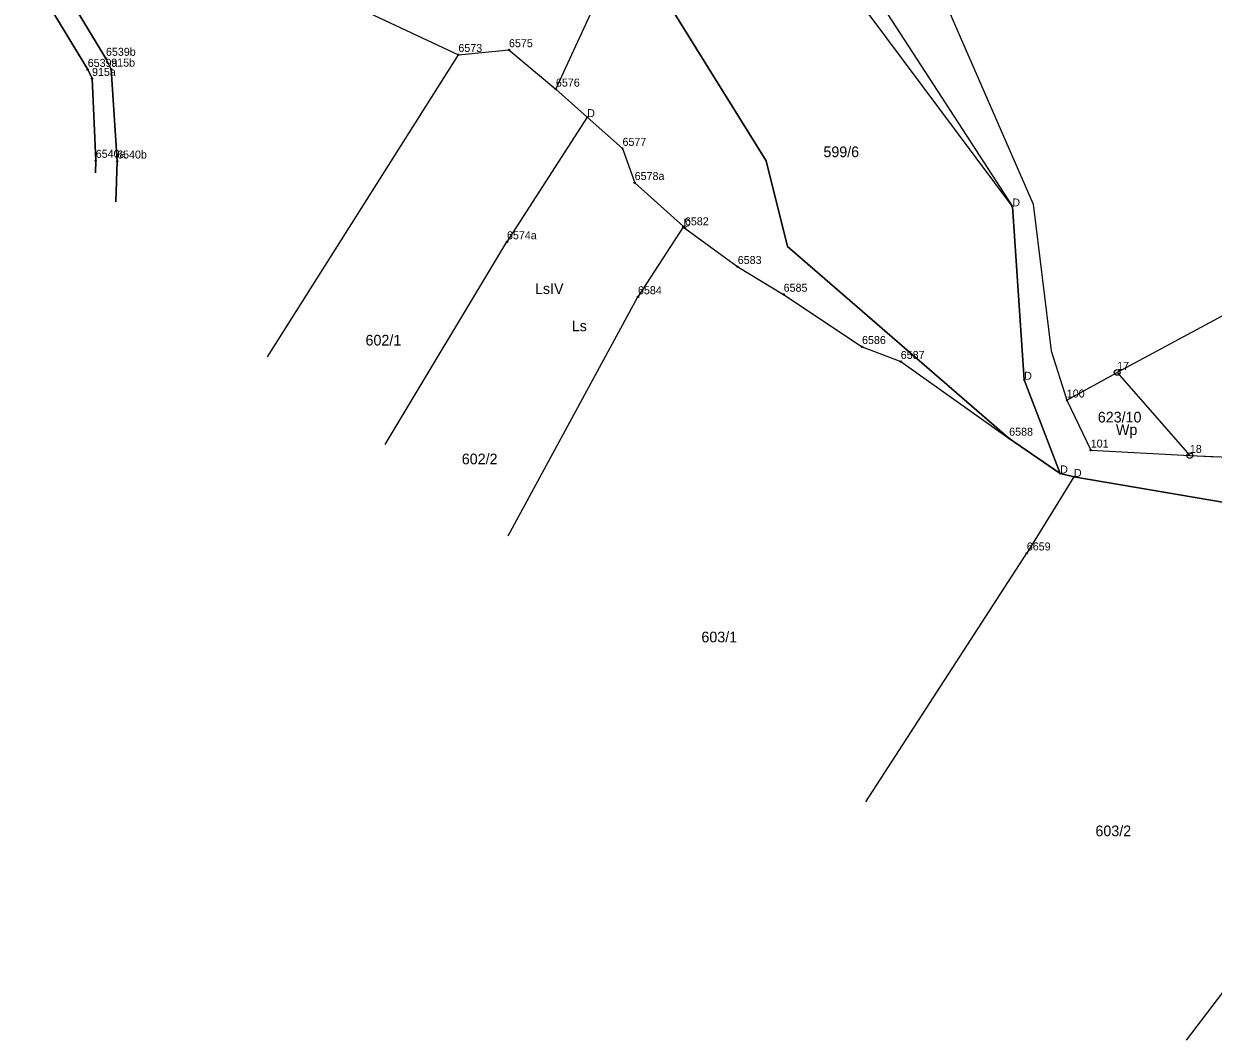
# Model space of a CAD drawing. Extents: x 7465393 to 7466459, y 5491258 to 5492404.
# Drawn here: x 7465794.3 to 7465961.5, y 5491455.4 to 5491598.3 of the extents above; entities that cross this region are included whole.
import ezdxf

# ---------------------------------------------------------------- set-up
doc = ezdxf.new("R2010")
doc.units = 0
for name, color, linetype in [('202-punkt graniczny', 7, 'Continuous'), ('202-punkt graniczny-Atr103', 7, 'Continuous'), ('203-punkt graniczny', 7, 'Continuous'), ('203-punkt graniczny-Atr103', 7, 'Continuous'), ('209-oznaczenie konturu klasyfikacyjnego', 7, 'Continuous'), ('210-oznaczenie konturu użytku gruntowego', 7, 'Continuous'), ('211-numer działki ewidencyjnej', 7, 'Continuous'), ('217-kontur klasyfikacyjny', 7, 'Continuous'), ('218-kontur użytku gruntowego', 7, 'Continuous'), ('219-działka ewidencyjna', 7, 'Continuous')]:
    doc.layers.add(name, color=color, linetype=linetype)

# ---------------------------------------------------------------- blocks, each defined once
blk = doc.blocks.new('203')
blk.add_circle((0, 0), 0.09)
blk = doc.blocks.new('202')
blk.add_circle((0, 0), 0.4)

msp = doc.modelspace()

# ---------------------------------------------------------------- linework, layer by layer
at = {"layer": '217-kontur klasyfikacyjny'}
for points in [[(7465796.9, 5491608.21), (7465805.83, 5491593.45)], [(7465898.65, 5491579.07), (7465880.35, 5491608.51)], [(7465803.27, 5491591.89), (7465794.28, 5491606.75)], [(7465805.83, 5491593.45), (7465806.57, 5491591.93)], [(7465803.87, 5491590.63), (7465803.27, 5491591.89)], [(7465806.57, 5491591.93), (7465807.4, 5491579.01)], [(7465804.4, 5491579.11), (7465803.87, 5491590.63)], [(7465804.34, 5491577.37), (7465804.4, 5491579.11)], [(7465807.4, 5491579.01), (7465807.2, 5491573.3)], [(7465901.61, 5491567.03), (7465898.65, 5491579.07)], [(7465932.79, 5491540.05), (7465901.61, 5491567.03)], [(7465939.96, 5491535.12), (7465932.79, 5491540.05)], [(7465941.89, 5491534.63), (7465939.96, 5491535.12)], [(7465980.11, 5491528.12), (7465941.89, 5491534.63)]]:
    msp.add_lwpolyline(points, dxfattribs=at)
at = {"layer": '218-kontur użytku gruntowego'}
for points in [[(7465890.56, 5491638.43), (7465933.24, 5491572.65)], [(7465933.24, 5491572.65), (7465892.52, 5491627.25)], [(7465805.83, 5491593.45), (7465796.9, 5491608.21)], [(7465880.35, 5491608.51), (7465898.65, 5491579.07)], [(7465794.28, 5491606.75), (7465803.27, 5491591.89)], [(7465923.67, 5491601.71), (7465936.16, 5491572.97)], [(7465806.57, 5491591.93), (7465805.83, 5491593.45)], [(7465803.27, 5491591.89), (7465803.87, 5491590.63)], [(7465807.4, 5491579.01), (7465806.57, 5491591.93)], [(7465803.87, 5491590.63), (7465804.4, 5491579.11)], [(7465804.4, 5491579.11), (7465804.34, 5491577.37)], [(7465807.2, 5491573.3), (7465807.4, 5491579.01)], [(7465898.65, 5491579.07), (7465901.61, 5491567.03)], [(7465934.9, 5491548.28), (7465933.24, 5491572.65)], [(7465936.16, 5491572.97), (7465938.68, 5491552.35)], [(7465901.61, 5491567.03), (7465932.79, 5491540.05)], [(7465938.68, 5491552.35), (7465940.89, 5491545.42)], [(7465939.96, 5491535.12), (7465934.9, 5491548.28)], [(7465940.89, 5491545.42), (7465947.97, 5491549.31)], [(7465947.97, 5491549.31), (7465958.19, 5491537.62)], [(7465940.89, 5491545.42), (7465944.26, 5491538.37)], [(7465932.79, 5491540.05), (7465939.96, 5491535.12)], [(7465944.26, 5491538.37), (7465958.19, 5491537.62)], [(7465958.19, 5491537.62), (7465962.06, 5491537.46)], [(7465941.89, 5491534.63), (7465939.96, 5491535.12)], [(7465980.11, 5491528.12), (7465941.89, 5491534.63)]]:
    msp.add_lwpolyline(points, dxfattribs=at)
at = {"layer": '219-działka ewidencyjna'}
for points in [[(7465933.24, 5491572.65), (7465892.52, 5491627.25)], [(7465796.9, 5491608.21), (7465805.83, 5491593.45)], [(7465794.28, 5491606.75), (7465803.27, 5491591.89)], [(7465869.08, 5491589.12), (7465875.59, 5491603.28)], [(7465839.89, 5491601.21), (7465855.37, 5491593.99)], [(7465805.83, 5491593.45), (7465806.57, 5491591.93)], [(7465828.54, 5491551.49), (7465855.37, 5491593.99)], [(7465855.37, 5491593.99), (7465862.48, 5491594.66)], [(7465862.48, 5491594.66), (7465869.08, 5491589.12)], [(7465803.27, 5491591.89), (7465803.87, 5491590.63)], [(7465806.57, 5491591.93), (7465807.4, 5491579.01)], [(7465803.87, 5491590.63), (7465804.4, 5491579.11)], [(7465873.48, 5491585.21), (7465869.08, 5491589.12)], [(7465873.48, 5491585.21), (7465862.2, 5491567.66)], [(7465873.48, 5491585.21), (7465878.44, 5491580.8)], [(7465878.44, 5491580.8), (7465880.15, 5491575.99)], [(7465804.34, 5491577.37), (7465804.4, 5491579.11)], [(7465807.2, 5491573.3), (7465807.4, 5491579.01)], [(7465886.99, 5491569.82), (7465880.15, 5491575.99)], [(7465933.24, 5491572.65), (7465934.9, 5491548.28)], [(7465989.35, 5491571.56), (7465947.97, 5491549.31)], [(7465886.99, 5491569.82), (7465880.61, 5491559.93)], [(7465886.99, 5491569.82), (7465887.21, 5491569.62)], [(7465887.21, 5491569.62), (7465894.64, 5491564.18)], [(7465845.09, 5491539.18), (7465862.2, 5491567.66)], [(7465894.64, 5491564.18), (7465901.09, 5491560.28)], [(7465862.35, 5491526.34), (7465880.61, 5491559.93)], [(7465901.09, 5491560.28), (7465912.11, 5491552.93)], [(7465912.11, 5491552.93), (7465917.55, 5491550.84)], [(7465917.55, 5491550.84), (7465932.79, 5491540.05)], [(7465934.9, 5491548.28), (7465939.96, 5491535.12)], [(7465940.89, 5491545.42), (7465947.97, 5491549.31)], [(7465947.97, 5491549.31), (7465958.19, 5491537.62)], [(7465940.89, 5491545.42), (7465944.26, 5491538.37)], [(7465939.96, 5491535.12), (7465932.79, 5491540.05)], [(7465944.26, 5491538.37), (7465958.19, 5491537.62)], [(7465958.19, 5491537.62), (7465980.12, 5491536.72)], [(7465941.89, 5491534.63), (7465935.27, 5491523.92)], [(7465939.96, 5491535.12), (7465941.89, 5491534.63)], [(7465941.89, 5491534.63), (7465980.11, 5491528.12)], [(7465912.65, 5491488.94), (7465935.27, 5491523.92)], [(7465957.71, 5491455.43), (7465969.3, 5491470.62)]]:
    msp.add_lwpolyline(points, dxfattribs=at)

# ---------------------------------------------------------------- block references
at = {"layer": '202-punkt graniczny'}
for p in [(7465947.97, 5491549.31), (7465958.19, 5491537.62)]:
    msp.add_blockref('202', p, dxfattribs=at)
at = {"layer": '203-punkt graniczny'}
for p in [(7465805.83, 5491593.45), (7465855.37, 5491593.99), (7465862.48, 5491594.66), (7465803.27, 5491591.89), (7465806.57, 5491591.93), (7465803.87, 5491590.63), (7465869.08, 5491589.12), (7465873.48, 5491585.21), (7465878.44, 5491580.8), (7465804.4, 5491579.11), (7465807.4, 5491579.01), (7465880.15, 5491575.99), (7465933.24, 5491572.65), (7465886.99, 5491569.82), (7465887.21, 5491569.62), (7465862.2, 5491567.66), (7465894.64, 5491564.18), (7465880.61, 5491559.93), (7465901.09, 5491560.28), (7465912.11, 5491552.93), (7465917.55, 5491550.84), (7465934.9, 5491548.28), (7465940.89, 5491545.42), (7465932.79, 5491540.05), (7465944.26, 5491538.37), (7465939.96, 5491535.12), (7465941.89, 5491534.63), (7465935.27, 5491523.92)]:
    msp.add_blockref('203', p, dxfattribs=at)

# ---------------------------------------------------------------- texts
at = {"layer": '202-punkt graniczny-Atr103'}
for s, p in [('17', (7465947.97, 5491549.68)), ('18', (7465958.19, 5491538))]:
    msp.add_text(s, height=1.125, dxfattribs=at).set_placement(p)
at = {"layer": '203-punkt graniczny-Atr103'}
for s, height, p in [('6539b', 1.125, (7465805.83, 5491593.83)), ('6573', 1.125, (7465855.37, 5491594.37)), ('6575', 1.125, (7465862.48, 5491595.04)), ('6539a', 1.125, (7465803.27, 5491592.27)), ('915b', 1.125, (7465806.57, 5491592.31)), ('915a', 1.125, (7465803.87, 5491591)), ('6576', 1.125, (7465869.08, 5491589.5)), ('D', 1.12, (7465873.48, 5491585.21)), ('6577', 1.125, (7465878.44, 5491581.17)), ('6540a', 1.125, (7465804.4, 5491579.49)), ('6540b', 1.125, (7465807.4, 5491579.39)), ('6578a', 1.125, (7465880.15, 5491576.37)), ('D', 1.12, (7465933.24, 5491572.65)), ('D', 1.12, (7465886.99, 5491569.82)), ('6582', 1.125, (7465887.21, 5491570)), ('6574a', 1.125, (7465862.2, 5491568.04)), ('6583', 1.125, (7465894.64, 5491564.56)), ('6584', 1.125, (7465880.61, 5491560.31)), ('6585', 1.125, (7465901.09, 5491560.66)), ('6586', 1.125, (7465912.11, 5491553.31)), ('6587', 1.125, (7465917.55, 5491551.21)), ('D', 1.12, (7465934.9, 5491548.28)), ('100', 1.125, (7465940.89, 5491545.79)), ('6588', 1.125, (7465932.79, 5491540.42)), ('101', 1.125, (7465944.26, 5491538.75)), ('D', 1.12, (7465939.96, 5491535.12)), ('D', 1.12, (7465941.89, 5491534.63)), ('6659', 1.125, (7465935.27, 5491524.29))]:
    msp.add_text(s, height=height, dxfattribs=at).set_placement(p)
at = {"layer": '209-oznaczenie konturu klasyfikacyjnego'}
msp.add_text('LsIV', height=1.5, dxfattribs=at).set_placement((7465866.14, 5491560.34))
at = {"layer": '210-oznaczenie konturu użytku gruntowego'}
for s, p in [('Ls', (7465871.3, 5491555.1)), ('Wp', (7465947.8, 5491540.52))]:
    msp.add_text(s, height=1.5, dxfattribs=at).set_placement(p)
at = {"layer": '211-numer działki ewidencyjnej'}
for s, p in [('599/6', (7465906.68, 5491579.58)), ('602/1', (7465842.32, 5491553.1)), ('623/10', (7465945.25, 5491542.28)), ('602/2', (7465855.85, 5491536.4)), ('603/1', (7465889.53, 5491511.37)), ('603/2', (7465944.92, 5491484.11))]:
    msp.add_text(s, height=1.5, dxfattribs=at).set_placement(p)

doc.saveas('drawing.dxf')
